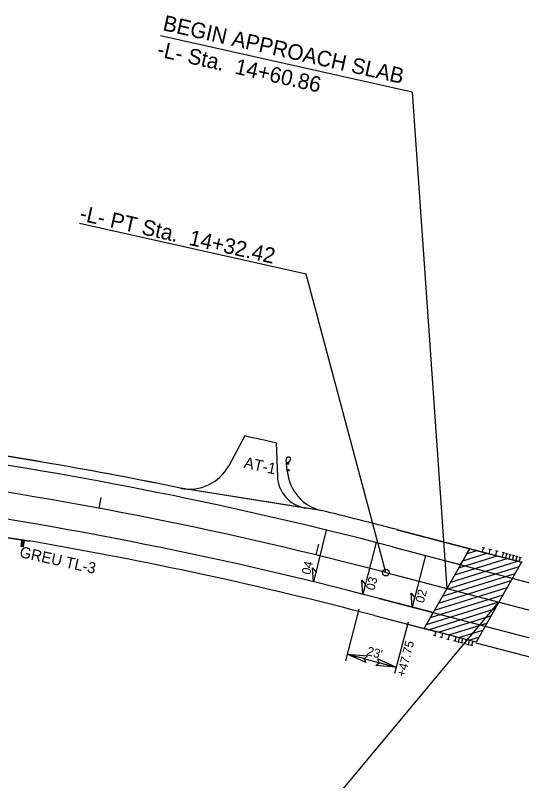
# Model space of a CAD drawing. Extents: x 1784740 to 1786163, y 841056 to 841833.
# Drawn here: x 1785226.5 to 1785454.6, y 841407.2 to 841752 of the extents above; entities that cross this region are included whole.
import ezdxf

# ---------------------------------------------------------------- set-up
doc = ezdxf.new("R2010")
doc.units = 0
for name, color, linetype in [('Old_Level_3', 7, 'Continuous'), ('Prop Approach Slab', 7, 'Continuous'), ('Prop Approach Slab Hatching', 7, 'Continuous'), ('Prop DSN Text', 7, 'Continuous'), ('Prop EOT', 7, 'Continuous'), ('Prop Guardrail', 7, 'Continuous'), ('Prop Guardrail Anchor Unit CELL', 7, 'Continuous'), ('Prop Horizontal Alignment', 7, 'Continuous'), ('Prop Horizontal Alignment Station Label', 7, 'Continuous'), ('Prop Horizontal Alignment Tick Small', 7, 'Continuous'), ('Prop Paved Shoulder', 7, 'Continuous'), ('Prop Roadway Bridge', 7, 'Continuous'), ('Prop Shade Light', 7, 'Continuous'), ('Prop Structure Anchor Unit CELL', 7, 'Continuous'), ('Prop Superelevation  Arrow CELL', 7, 'Continuous'), ('Prop Superelevation Label', 7, 'Continuous'), ('Prop Terminator CELL', 7, 'Continuous')]:
    doc.layers.add(name, color=color, linetype=linetype)

msp = doc.modelspace()

# ---------------------------------------------------------------- linework, layer by layer
at = {"layer": 'Old_Level_3'}
for p, q in [((1785329.82, 841562.5), (1785322.58, 841549.08)), ((1785343.92, 841559.36), (1785344.53, 841544.25))]:
    msp.add_line(p, q, dxfattribs=at)
for centre, radius, start, end in [((1784924.4, 839711.38), 1895, 77.20997, 77.64668), ((1785304.98, 841558.58), 20, 258.3583, 331.658), ((1785359.52, 841544.86), 15, 182.337, 260.9581)]:
    msp.add_arc(centre, radius, start, end, dxfattribs=at)
at = {"layer": 'Prop Approach Slab'}
msp.add_lwpolyline([(1785410.64, 841475.75), (1785431.15, 841511.72), (1785454.5, 841505.6), (1785434, 841469.63)], close=True, dxfattribs=at)
at = {"layer": 'Prop Approach Slab Hatching'}
for p, q in [((1785428.04, 841506.27), (1785438.95, 841509.68)), ((1785429.86, 841509.45), (1785434.4, 841510.87)), ((1785422.59, 841496.71), (1785452.63, 841506.1)), ((1785424.41, 841499.89), (1785448.07, 841507.29)), ((1785426.23, 841503.08), (1785443.51, 841508.48)), ((1785442.65, 841508.21), (1785443.51, 841508.48)), ((1785420.78, 841493.52), (1785453.44, 841503.73)), ((1785418.96, 841490.33), (1785451.62, 841500.54)), ((1785417.14, 841487.14), (1785449.8, 841497.35)), ((1785415.32, 841483.96), (1785447.98, 841494.17)), ((1785413.51, 841480.77), (1785446.17, 841490.98)), ((1785411.69, 841477.58), (1785444.35, 841487.79)), ((1785412.58, 841475.24), (1785442.53, 841484.6)), ((1785417.14, 841474.05), (1785440.72, 841481.42)), ((1785421.69, 841472.85), (1785438.9, 841478.23)), ((1785426.25, 841471.66), (1785437.08, 841475.04)), ((1785430.81, 841470.46), (1785435.27, 841471.86))]:
    msp.add_line(p, q, dxfattribs=at)
at = {"layer": 'Prop DSN Text'}
for p, q in [((1785405.19, 841717.36), (1785291.92, 841742.77)), ((1785405.19, 841717.36), (1785420.9, 841493.73)), ((1785315.08, 841332.87), (1785444.25, 841487.62))]:
    msp.add_line(p, q, dxfattribs=at)
at = {"layer": 'Prop EOT'}
for p, q in [((1785396.43, 841512.55), (1785733.71, 841424.16)), ((1785390.34, 841489.34), (1785642.41, 841423.28))]:
    msp.add_line(p, q, dxfattribs=at)
for radius, end in [(1862, 81.98136), (1838, 82.51319)]:
    msp.add_arc((1784924.4, 839711.38), radius, 75.31501, end, dxfattribs=at)
at = {"layer": 'Prop Guardrail'}
for p, q in [((1785436.83, 841510.23), (1785398.46, 841520.29)), ((1785388.32, 841481.6), (1785415.86, 841474.38))]:
    msp.add_line(p, q, dxfattribs=at)
for centre, radius, start, end in [((1785368.9, 841548.36), 20, 184.7778, 256.3975), ((1784924.4, 839711.38), 1870, 75.31501, 76.39749), ((1784924.4, 839711.38), 1830, 75.31501, 80.29419)]:
    msp.add_arc(centre, radius, start, end, dxfattribs=at)
at = {"layer": 'Prop Guardrail Anchor Unit CELL'}
for p, q in [((1785348.68, 841550.23), (1785348.53, 841551.94)), ((1785348.65, 841550.49), (1785349.46, 841550.56)), ((1785348.65, 841550.49), (1785349.01, 841550.52)), ((1785348.65, 841550.49), (1785349.01, 841550.52)), ((1785348.71, 841549.8), (1785348.65, 841550.49)), ((1785348.65, 841550.49), (1785349.52, 841549.86)), ((1785348.67, 841550.36), (1785348.68, 841550.23)), ((1785348.67, 841550.36), (1785348.68, 841550.23)), ((1785348.97, 841546.7), (1785348.68, 841550.23)), ((1785348.71, 841549.8), (1785349.46, 841550.56)), ((1785350.18, 841551.28), (1785349.36, 841550.55)), ((1785349.46, 841550.56), (1785349.52, 841549.86)), ((1785349.52, 841549.86), (1785348.71, 841549.8)), ((1785348.91, 841547.4), (1785349.72, 841547.46)), ((1785348.97, 841546.7), (1785348.91, 841547.4)), ((1785348.91, 841547.4), (1785349.78, 841546.76)), ((1785348.97, 841546.7), (1785349.72, 841547.46)), ((1785349.78, 841546.76), (1785348.97, 841546.7)), ((1785349.72, 841547.46), (1785349.78, 841546.76)), ((1785232.92, 841515.18), (1785186.71, 841522.27)), ((1785229.42, 841515.72), (1785228.97, 841512.75)), ((1785229.42, 841515.72), (1785229.19, 841514.24)), ((1785230.41, 841515.57), (1785229.42, 841515.72)), ((1785230.18, 841514.09), (1785229.42, 841515.72)), ((1785228.97, 841512.75), (1785230.18, 841514.09)), ((1785229.95, 841512.6), (1785228.97, 841512.75)), ((1785229.19, 841514.24), (1785230.41, 841515.57)), ((1785230.18, 841514.09), (1785229.19, 841514.24)), ((1785229.19, 841514.24), (1785229.95, 841512.6)), ((1785230.41, 841515.57), (1785229.95, 841512.6))]:
    msp.add_line(p, q, dxfattribs=at)
msp.add_ellipse((1785349.52, 841552.02), major_axis=(-0.99, -0.083), ratio=0.995379, start_param=2.210226, end_param=6.283185, dxfattribs=at)
at = {"layer": 'Prop Horizontal Alignment'}
msp.add_line((1785393.39, 841500.94), (1785730.66, 841412.56), dxfattribs=at)
msp.add_arc((1784924.4, 839711.38), 1850, 75.31501, 88.70732, dxfattribs=at)
at = {"layer": 'Prop Horizontal Alignment Station Label'}
for p, q in [((1785357.48, 841635.36), (1785255.36, 841658.26)), ((1785393.39, 841500.94), (1785357.48, 841635.36))]:
    msp.add_line(p, q, dxfattribs=at)
msp.add_circle((1785393.39, 841500.94), 1.5, dxfattribs=at)
at = {"layer": 'Prop Horizontal Alignment Tick Small'}
for p, q in [((1785264.2, 841529.9), (1785265.12, 841534.82)), ((1785361.96, 841508.89), (1785363.14, 841513.75))]:
    msp.add_line(p, q, dxfattribs=at)
at = {"layer": 'Prop Paved Shoulder'}
for p, q in [((1785364.2, 841528.93), (1785300.94, 841538.99)), ((1785232.92, 841515.18), (1785186.71, 841522.27)), ((1785398.46, 841520.29), (1785431.15, 841511.72)), ((1785388.32, 841481.6), (1785411.68, 841475.48))]:
    msp.add_line(p, q, dxfattribs=at)
for radius, start, end in [(1866, 78.35834, 81.98136), (1870, 75.31501, 76.39761), (1830, 75.31501, 80.29419)]:
    msp.add_arc((1784924.4, 839711.38), radius, start, end, dxfattribs=at)
at = {"layer": 'Prop Roadway Bridge'}
for p, q in [((1785454.5, 841505.6), (1785434, 841469.63)), ((1785433.91, 841469.3), (1785617.71, 841421.14))]:
    msp.add_line(p, q, dxfattribs=at)
at = {"layer": 'Prop Shade Light'}
for p, q in [((1785186.71, 841522.27), (1785232.92, 841515.18)), ((1785431.15, 841511.72), (1785398.46, 841520.29)), ((1785414.75, 841482.94), (1785390.34, 841489.34)), ((1785388.32, 841481.6), (1785410.64, 841475.75)), ((1785410.64, 841475.75), (1785414.75, 841482.94))]:
    msp.add_line(p, q, dxfattribs=at)
for points in [[(1785364.2, 841528.93), (1785357.16, 841530.04), (1785302.74, 841538.71)], [(1785396.43, 841512.55), (1785411.26, 841508.67), (1785427.05, 841504.53)], [(1785427.05, 841504.53), (1785428.04, 841506.27), (1785429.86, 841509.45), (1785431.15, 841511.72)]]:
    msp.add_lwpolyline(points, dxfattribs=at)
for centre, radius, start, end in [((1784924.4, 839711.38), 1866, 78.35834, 81.97421), ((1784924.4, 839711.38), 1862, 75.31501, 81.98136), ((1785304.98, 841558.58), 20, 258.3583, 263.5579), ((1784924.4, 839711.38), 1838, 75.31501, 82.51319), ((1784924.4, 839711.38), 1870, 75.31501, 76.39761), ((1784924.4, 839711.38), 1830, 75.31501, 80.29419)]:
    msp.add_arc(centre, radius, start, end, dxfattribs=at)
at = {"layer": 'Prop Structure Anchor Unit CELL'}
for p, q in [((1785437.89, 841512.02), (1785436.78, 841512.31)), ((1785436.83, 841510.23), (1785437.34, 841512.17)), ((1785454.97, 841505.48), (1785436.83, 841510.23)), ((1785440.92, 841511.23), (1785439.81, 841511.52)), ((1785439.85, 841509.44), (1785440.36, 841511.38)), ((1785443.94, 841510.44), (1785442.83, 841510.73)), ((1785442.88, 841508.65), (1785443.38, 841510.59)), ((1785446.96, 841509.65), (1785445.85, 841509.94)), ((1785445.9, 841507.86), (1785446.41, 841509.79)), ((1785448.47, 841509.25), (1785447.36, 841509.54)), ((1785447.41, 841507.46), (1785447.92, 841509.4)), ((1785449.98, 841508.86), (1785448.88, 841509.15)), ((1785448.92, 841507.07), (1785449.43, 841509)), ((1785451.5, 841508.46), (1785450.39, 841508.75)), ((1785450.43, 841506.67), (1785450.94, 841508.6)), ((1785453.01, 841508.06), (1785451.9, 841508.35)), ((1785451.95, 841506.27), (1785452.45, 841508.21)), ((1785454.52, 841507.67), (1785453.41, 841507.96)), ((1785453.46, 841505.88), (1785453.96, 841507.81)), ((1785415.86, 841474.38), (1785415.35, 841472.45)), ((1785434, 841469.63), (1785415.86, 841474.38)), ((1785415.91, 841472.3), (1785414.8, 841472.59)), ((1785418.93, 841471.51), (1785417.82, 841471.8)), ((1785418.88, 841473.59), (1785418.37, 841471.65)), ((1785421.95, 841470.72), (1785420.84, 841471.01)), ((1785421.9, 841472.8), (1785421.4, 841470.86)), ((1785424.93, 841472), (1785424.42, 841470.07)), ((1785426.44, 841471.61), (1785425.93, 841469.67)), ((1785427.95, 841471.21), (1785427.44, 841469.28)), ((1785424.97, 841469.92), (1785423.87, 841470.21)), ((1785426.49, 841469.53), (1785425.38, 841469.82)), ((1785428, 841469.13), (1785426.89, 841469.42)), ((1785429.51, 841468.74), (1785428.4, 841469.03)), ((1785429.46, 841470.82), (1785428.95, 841468.88)), ((1785431.02, 841468.34), (1785429.91, 841468.63)), ((1785430.97, 841470.42), (1785430.47, 841468.48)), ((1785432.53, 841467.94), (1785431.42, 841468.23)), ((1785432.48, 841470.02), (1785431.98, 841468.09))]:
    msp.add_line(p, q, dxfattribs=at)
at = {"layer": 'Prop Superelevation  Arrow CELL'}
for points in [[(1785360.81, 841496.82), (1785360.29, 841503.12), (1785361.91, 841501.31)], [(1785382.97, 841491.25), (1785382.53, 841497.56), (1785384.12, 841495.73)], [(1785405.18, 841485.45), (1785404.76, 841491.76), (1785406.35, 841489.92)]]:
    msp.add_lwpolyline(points, close=True, dxfattribs=at)
at = {"layer": 'Prop Superelevation Label'}
for p, q in [((1785366.51, 841520.13), (1785360.81, 841496.82)), ((1785388.96, 841514.49), (1785382.97, 841491.25)), ((1785411.26, 841508.67), (1785405.18, 841485.45)), ((1785381.22, 841484.47), (1785375.24, 841461.23)), ((1785403.4, 841478.68), (1785397.32, 841455.46)), ((1785383.25, 841462.25), (1785398.08, 841458.37))]:
    msp.add_line(p, q, dxfattribs=at)
msp.add_arc((1784924.4, 839711.38), 1810, 75.31501, 75.55252, dxfattribs=at)
at = {"layer": 'Prop Terminator CELL'}
for points in [[(1785384.31, 841460.39), (1785375.98, 841464.14), (1785385.15, 841463.43), (1785383.63, 841462.17)], [(1785389.76, 841462.15), (1785398.08, 841458.37), (1785388.92, 841459.11), (1785390.43, 841460.37)]]:
    msp.add_lwpolyline(points, close=True, dxfattribs=at)

# ---------------------------------------------------------------- texts
at = {"layer": 'Prop DSN Text'}
for s, p in [('BEGIN APPROACH SLAB', (1785292.55, 841745.31)), ('-L- Sta.  14+60.86', (1785289.92, 841733.6))]:
    msp.add_text(s, height=7, rotation=347.3599, dxfattribs=at).set_placement(p)
at = {"layer": 'Prop Guardrail Anchor Unit CELL'}
for s, p in [('AT-1', (1785329.15, 841548.31)), ('GREU TL-3', (1785228.08, 841507.99))]:
    msp.add_text(s, height=5, rotation=347.3599, dxfattribs=at).set_placement(p)
at = {"layer": 'Prop Horizontal Alignment Station Label'}
msp.add_text('-L- PT Sta.  14+32.42', height=7, rotation=347.3599, dxfattribs=at).set_placement((1785255.03, 841659.66))
at = {"layer": 'Prop Superelevation Label'}
for s, rotation, p in [('04', 76.2648, (1785359.23, 841499.75)), ('03', 75.5525, (1785388.18, 841492.7)), ('02', 75.315, (1785410.43, 841487.02)), ("23'", 345.315, (1785384.5, 841463.84)), ('+47.75', 75.315, (1785402.01, 841453.69))]:
    msp.add_text(s, height=4, rotation=rotation, dxfattribs=at).set_placement(p)

doc.saveas('drawing.dxf')
